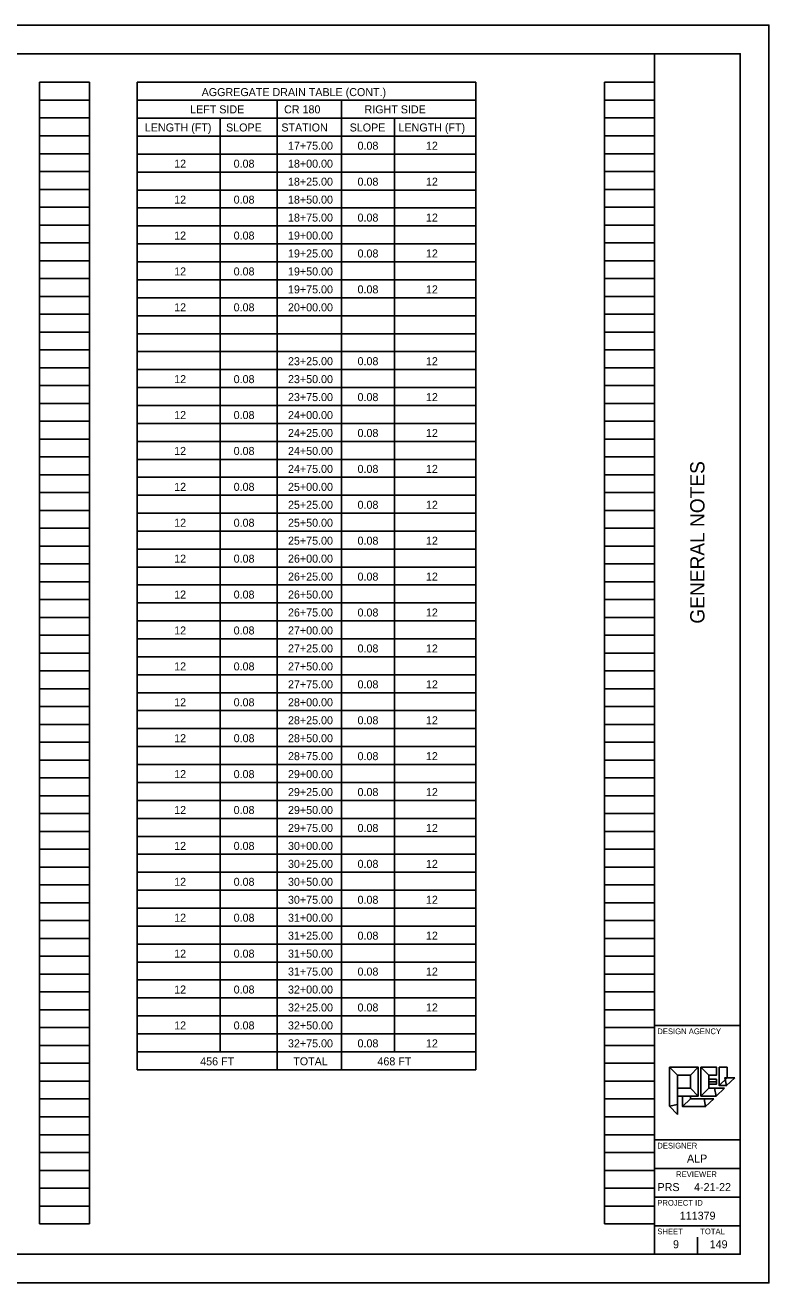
# Model space of a CAD drawing. Extents: x -0.5 to 34, y 0 to 22.
# Drawn here: x 21 to 34, y 0 to 22 of the extents above; entities that cross this region are included whole.
import ezdxf

# ---------------------------------------------------------------- set-up
doc = ezdxf.new("R2010")
doc.units = 0
for name, color, linetype in [('Default', 7, 'Continuous'), ('SC_Scratch1', 7, 'Continuous'), ('SH_Border', 7, 'Continuous'), ('SH_Cut_Line', 7, 'Continuous'), ('SH_Data', 7, 'Continuous'), ('SH_Text', 7, 'Continuous')]:
    doc.layers.add(name, color=color, linetype=linetype)

msp = doc.modelspace()

# ---------------------------------------------------------------- linework, layer by layer
at = {"layer": 'Default'}
msp.add_line((32.95, 3.519), (33.087, 3.519), dxfattribs=at)
for points in [[(32.264, 3.093), (32.264, 3.77), (32.401, 3.633), (32.401, 3.121)], [(32.264, 3.77), (32.767, 3.77), (32.63, 3.633), (32.401, 3.633)], [(32.767, 3.77), (32.767, 3.267), (32.63, 3.404), (32.63, 3.633)], [(32.812, 3.267), (32.812, 3.77), (32.95, 3.633), (32.95, 3.404)], [(32.812, 3.77), (33.087, 3.77), (33.087, 3.633), (32.95, 3.633)], [(33.132, 3.45), (33.132, 3.77), (33.27, 3.77), (33.27, 3.587)], [(33.087, 3.56), (33.087, 3.477), (32.951, 3.477), (32.951, 3.56)], [(33.261, 3.45), (33.132, 3.45), (33.27, 3.587), (33.233, 3.587)], [(33.407, 3.587), (33.261, 3.45), (33.233, 3.587)], [(32.767, 3.267), (32.401, 3.267), (32.401, 3.404), (32.63, 3.404)], [(33.078, 3.267), (32.812, 3.267), (32.95, 3.404), (33.05, 3.404)], [(33.224, 3.404), (33.078, 3.267), (33.05, 3.404)], [(32.401, 2.947), (32.264, 3.093), (32.401, 3.121)], [(32.492, 3.084), (32.492, 3.267), (32.63, 3.267), (32.63, 3.221)], [(32.895, 3.084), (32.492, 3.084), (32.63, 3.221), (32.867, 3.221)], [(33.041, 3.221), (32.895, 3.084), (32.867, 3.221)]]:
    msp.add_lwpolyline(points, close=True, dxfattribs=at)
at = {"layer": 'SC_Scratch1'}
for p, q in [((21.25, 1.032), (21.25, 21)), ((21.25, 21), (22.125, 21)), ((22.125, 1.032), (22.125, 21)), ((31.125, 1.032), (31.125, 21)), ((31.125, 21), (32, 21)), ((32, 1.032), (32, 21)), ((21.25, 20.688), (22.125, 20.688)), ((31.125, 20.688), (32, 20.688)), ((21.25, 20.376), (22.125, 20.376)), ((31.125, 20.376), (32, 20.376)), ((21.25, 20.064), (22.125, 20.064)), ((31.125, 20.064), (32, 20.064)), ((21.25, 19.752), (22.125, 19.752)), ((31.125, 19.752), (32, 19.752)), ((21.25, 19.44), (22.125, 19.44)), ((31.125, 19.44), (32, 19.44)), ((21.25, 19.128), (22.125, 19.128)), ((31.125, 19.128), (32, 19.128)), ((21.25, 18.816), (22.125, 18.816)), ((31.125, 18.816), (32, 18.816)), ((21.25, 18.504), (22.125, 18.504)), ((31.125, 18.504), (32, 18.504)), ((21.25, 18.192), (22.125, 18.192)), ((31.125, 18.192), (32, 18.192)), ((21.25, 17.88), (22.125, 17.88)), ((31.125, 17.88), (32, 17.88)), ((21.25, 17.568), (22.125, 17.568)), ((31.125, 17.568), (32, 17.568)), ((21.25, 17.256), (22.125, 17.256)), ((31.125, 17.256), (32, 17.256)), ((21.25, 16.944), (22.125, 16.944)), ((31.125, 16.944), (32, 16.944)), ((21.25, 16.632), (22.125, 16.632)), ((31.125, 16.632), (32, 16.632)), ((21.25, 16.32), (22.125, 16.32)), ((31.125, 16.32), (32, 16.32)), ((21.25, 16.008), (22.125, 16.008)), ((31.125, 16.008), (32, 16.008)), ((21.25, 15.696), (22.125, 15.696)), ((31.125, 15.696), (32, 15.696)), ((21.25, 15.384), (22.125, 15.384)), ((31.125, 15.384), (32, 15.384)), ((21.25, 15.072), (22.125, 15.072)), ((31.125, 15.072), (32, 15.072)), ((21.25, 14.76), (22.125, 14.76)), ((31.125, 14.76), (32, 14.76)), ((21.25, 14.448), (22.125, 14.448)), ((31.125, 14.448), (32, 14.448)), ((21.25, 14.136), (22.125, 14.136)), ((31.125, 14.136), (32, 14.136)), ((21.25, 13.824), (22.125, 13.824)), ((31.125, 13.824), (32, 13.824)), ((21.25, 13.512), (22.125, 13.512)), ((31.125, 13.512), (32, 13.512)), ((21.25, 13.2), (22.125, 13.2)), ((31.125, 13.2), (32, 13.2)), ((21.25, 12.888), (22.125, 12.888)), ((31.125, 12.888), (32, 12.888)), ((21.25, 12.576), (22.125, 12.576)), ((31.125, 12.576), (32, 12.576)), ((21.25, 12.264), (22.125, 12.264)), ((31.125, 12.264), (32, 12.264)), ((21.25, 11.952), (22.125, 11.952)), ((31.125, 11.952), (32, 11.952)), ((21.25, 11.64), (22.125, 11.64)), ((31.125, 11.64), (32, 11.64)), ((21.25, 11.328), (22.125, 11.328)), ((31.125, 11.328), (32, 11.328)), ((21.25, 11.016), (22.125, 11.016)), ((31.125, 11.016), (32, 11.016)), ((21.25, 10.704), (22.125, 10.704)), ((31.125, 10.704), (32, 10.704)), ((21.25, 10.392), (22.125, 10.392)), ((31.125, 10.392), (32, 10.392)), ((21.25, 10.08), (22.125, 10.08)), ((31.125, 10.08), (32, 10.08)), ((21.25, 9.768), (22.125, 9.768)), ((31.125, 9.768), (32, 9.768)), ((21.25, 9.456), (22.125, 9.456)), ((31.125, 9.456), (32, 9.456)), ((21.25, 9.144), (22.125, 9.144)), ((31.125, 9.144), (32, 9.144)), ((21.25, 8.832), (22.125, 8.832)), ((31.125, 8.832), (32, 8.832)), ((21.25, 8.52), (22.125, 8.52)), ((31.125, 8.52), (32, 8.52)), ((21.25, 8.208), (22.125, 8.208)), ((31.125, 8.208), (32, 8.208)), ((21.25, 7.896), (22.125, 7.896)), ((31.125, 7.896), (32, 7.896)), ((21.25, 7.584), (22.125, 7.584)), ((31.125, 7.584), (32, 7.584)), ((21.25, 7.272), (22.125, 7.272)), ((31.125, 7.272), (32, 7.272)), ((21.25, 6.96), (22.125, 6.96)), ((31.125, 6.96), (32, 6.96)), ((21.25, 6.648), (22.125, 6.648)), ((31.125, 6.648), (32, 6.648)), ((21.25, 6.336), (22.125, 6.336)), ((31.125, 6.336), (32, 6.336)), ((21.25, 6.024), (22.125, 6.024)), ((31.125, 6.024), (32, 6.024)), ((21.25, 5.712), (22.125, 5.712)), ((31.125, 5.712), (32, 5.712)), ((21.25, 5.4), (22.125, 5.4)), ((31.125, 5.4), (32, 5.4)), ((21.25, 5.088), (22.125, 5.088)), ((31.125, 5.088), (32, 5.088)), ((21.25, 4.776), (22.125, 4.776)), ((31.125, 4.776), (32, 4.776)), ((21.25, 4.464), (22.125, 4.464)), ((31.125, 4.464), (32, 4.464)), ((21.25, 4.152), (22.125, 4.152)), ((31.125, 4.152), (32, 4.152)), ((21.25, 3.84), (22.125, 3.84)), ((31.125, 3.84), (32, 3.84)), ((21.25, 3.528), (22.125, 3.528)), ((31.125, 3.528), (32, 3.528)), ((21.25, 3.216), (22.125, 3.216)), ((31.125, 3.216), (32, 3.216)), ((21.25, 2.904), (22.125, 2.904)), ((31.125, 2.904), (32, 2.904)), ((21.25, 2.592), (22.125, 2.592)), ((31.125, 2.592), (32, 2.592)), ((21.25, 2.28), (22.125, 2.28)), ((31.125, 2.28), (32, 2.28)), ((21.25, 1.968), (22.125, 1.968)), ((31.125, 1.968), (32, 1.968)), ((21.25, 1.656), (22.125, 1.656)), ((31.125, 1.656), (32, 1.656)), ((21.25, 1.344), (22.125, 1.344)), ((31.125, 1.344), (32, 1.344)), ((21.25, 1.032), (22.125, 1.032)), ((31.125, 1.032), (32, 1.032))]:
    msp.add_line(p, q, dxfattribs=at)
at = {"layer": 'SH_Border'}
for p, q in [((32, 0.5), (32, 21.5)), ((32, 4.5), (33.5, 4.5)), ((32, 2.5), (33.5, 2.5)), ((32, 2), (33.5, 2)), ((32, 1.5), (33.5, 1.5)), ((32, 1), (33.5, 1))]:
    msp.add_line(p, q, dxfattribs=at)
msp.add_lwpolyline([(1.5, 21.5), (33.5, 21.5), (33.5, 0.5), (1.5, 0.5)], close=True, dxfattribs=at)
at = {"layer": 'SH_Cut_Line'}
msp.add_lwpolyline([(0, 0), (34, 0), (34, 22), (0, 22)], close=True, dxfattribs=at)
at = {"layer": 'SH_Data'}
for p, q in [((32.75, 3.5), (32.75, 3.5)), ((32.75, 0.5), (32.75, 0.8))]:
    msp.add_line(p, q, dxfattribs=at)
at = {"layer": 'SH_Text'}
for p, q in [((22.956, 21), (28.88, 21)), ((22.956, 21), (22.956, 3.728)), ((28.88, 21), (28.88, 3.728)), ((22.956, 20.686), (28.88, 20.686)), ((25.404, 20.686), (25.404, 3.728)), ((26.531, 20.686), (26.531, 3.728)), ((22.956, 20.372), (28.88, 20.372)), ((24.406, 20.372), (24.406, 4.042)), ((27.457, 20.372), (27.457, 4.042)), ((22.956, 20.058), (28.88, 20.058)), ((22.956, 19.744), (28.88, 19.744)), ((22.956, 19.43), (28.88, 19.43)), ((22.956, 19.116), (28.88, 19.116)), ((22.956, 18.802), (28.88, 18.802)), ((22.956, 18.488), (28.88, 18.488)), ((22.956, 18.174), (28.88, 18.174)), ((22.956, 17.86), (28.88, 17.86)), ((22.956, 17.546), (28.88, 17.546)), ((22.956, 17.231), (28.88, 17.231)), ((22.956, 16.917), (28.88, 16.917)), ((22.956, 16.603), (28.88, 16.603)), ((22.956, 16.289), (28.88, 16.289)), ((22.956, 15.975), (28.88, 15.975)), ((22.956, 15.661), (28.88, 15.661)), ((22.956, 15.347), (28.88, 15.347)), ((22.956, 15.033), (28.88, 15.033)), ((22.956, 14.719), (28.88, 14.719)), ((22.956, 14.405), (28.88, 14.405)), ((22.956, 14.091), (28.88, 14.091)), ((22.956, 13.777), (28.88, 13.777)), ((22.956, 13.463), (28.88, 13.463)), ((22.956, 13.149), (28.88, 13.149)), ((22.956, 12.835), (28.88, 12.835)), ((22.956, 12.521), (28.88, 12.521)), ((22.956, 12.207), (28.88, 12.207)), ((22.956, 11.893), (28.88, 11.893)), ((22.956, 11.579), (28.88, 11.579)), ((22.956, 11.265), (28.88, 11.265)), ((22.956, 10.951), (28.88, 10.951)), ((22.956, 10.637), (28.88, 10.637)), ((22.956, 10.323), (28.88, 10.323)), ((22.956, 10.009), (28.88, 10.009)), ((22.956, 9.695), (28.88, 9.695)), ((22.956, 9.38), (28.88, 9.38)), ((22.956, 9.066), (28.88, 9.066)), ((22.956, 8.752), (28.88, 8.752)), ((22.956, 8.438), (28.88, 8.438)), ((22.956, 8.124), (28.88, 8.124)), ((22.956, 7.81), (28.88, 7.81)), ((22.956, 7.496), (28.88, 7.496)), ((22.956, 7.182), (28.88, 7.182)), ((22.956, 6.868), (28.88, 6.868)), ((22.956, 6.554), (28.88, 6.554)), ((22.956, 6.24), (28.88, 6.24)), ((22.956, 5.926), (28.88, 5.926)), ((22.956, 5.612), (28.88, 5.612)), ((22.956, 5.298), (28.88, 5.298)), ((22.956, 4.984), (28.88, 4.984)), ((22.956, 4.67), (28.88, 4.67)), ((22.956, 4.356), (28.88, 4.356)), ((22.956, 4.042), (28.88, 4.042)), ((22.956, 3.728), (28.88, 3.728))]:
    msp.add_line(p, q, dxfattribs=at)

# ---------------------------------------------------------------- texts
at = {"layer": 'SH_Data'}
msp.add_text('GENERAL NOTES', height=0.25, rotation=90, dxfattribs=at).set_placement((32.875, 11.531))
for s, height, p in [('DESIGN AGENCY', 0.1, (32.05, 4.35)), ('DESIGNER', 0.1, (32.05, 2.35)), ('ALP', 0.14, (32.569, 2.105)), ('REVIEWER', 0.1, (32.378, 1.85)), ('PRS', 0.14, (32.054, 1.605)), ('4-21-22', 0.14, (32.693, 1.605)), ('PROJECT ID', 0.1, (32.05, 1.35)), ('111379', 0.14, (32.443, 1.105)), ('SHEET', 0.1, (32.05, 0.85)), ('TOTAL', 0.1, (32.8, 0.85)), ('9', 0.14, (32.325, 0.605)), ('149', 0.14, (32.966, 0.605))]:
    msp.add_text(s, height=height, dxfattribs=at).set_placement(p)
at = {"layer": 'SH_Text'}
for s, p in [('AGGREGATE DRAIN TABLE (CONT.)', (24.084, 20.759)), ('LEFT SIDE', (23.882, 20.457)), ('CR 180', (25.525, 20.457)), ('RIGHT SIDE', (26.931, 20.457)), ('LENGTH (FT)', (23.09, 20.14)), ('SLOPE', (24.51, 20.14)), ('STATION', (25.477, 20.14)), ('SLOPE', (26.671, 20.14)), ('LENGTH (FT)', (27.525, 20.14)), ('17+75.00', (25.593, 19.821)), ('0.08', (26.809, 19.821)), ('12', (28.005, 19.821)), ('12', (23.603, 19.507)), ('0.08', (24.643, 19.507)), ('18+00.00', (25.593, 19.507)), ('18+25.00', (25.593, 19.192)), ('0.08', (26.809, 19.192)), ('12', (28.005, 19.192)), ('12', (23.603, 18.878)), ('0.08', (24.643, 18.878)), ('18+50.00', (25.593, 18.878)), ('18+75.00', (25.593, 18.564)), ('0.08', (26.809, 18.564)), ('12', (28.005, 18.564)), ('12', (23.603, 18.25)), ('0.08', (24.643, 18.25)), ('19+00.00', (25.593, 18.25)), ('19+25.00', (25.593, 17.936)), ('0.08', (26.809, 17.936)), ('12', (28.005, 17.936)), ('12', (23.603, 17.622)), ('0.08', (24.643, 17.622)), ('19+50.00', (25.593, 17.622)), ('19+75.00', (25.593, 17.308)), ('0.08', (26.809, 17.308)), ('12', (28.005, 17.308)), ('12', (23.603, 16.994)), ('0.08', (24.643, 16.994)), ('20+00.00', (25.593, 16.994)), ('23+25.00', (25.593, 16.052)), ('0.08', (26.809, 16.052)), ('12', (28.005, 16.052)), ('12', (23.603, 15.738)), ('0.08', (24.643, 15.738)), ('23+50.00', (25.593, 15.738)), ('23+75.00', (25.593, 15.424)), ('0.08', (26.809, 15.424)), ('12', (28.005, 15.424)), ('12', (23.603, 15.11)), ('0.08', (24.643, 15.11)), ('24+00.00', (25.593, 15.11)), ('24+25.00', (25.593, 14.796)), ('0.08', (26.809, 14.796)), ('12', (28.005, 14.796)), ('12', (23.603, 14.482)), ('0.08', (24.643, 14.482)), ('24+50.00', (25.593, 14.482)), ('24+75.00', (25.593, 14.168)), ('0.08', (26.809, 14.168)), ('12', (28.005, 14.168)), ('12', (23.603, 13.854)), ('0.08', (24.643, 13.854)), ('25+00.00', (25.593, 13.854)), ('25+25.00', (25.593, 13.54)), ('0.08', (26.809, 13.54)), ('12', (28.005, 13.54)), ('12', (23.603, 13.226)), ('0.08', (24.643, 13.226)), ('25+50.00', (25.593, 13.226)), ('25+75.00', (25.593, 12.912)), ('0.08', (26.809, 12.912)), ('12', (28.005, 12.912)), ('12', (23.603, 12.598)), ('0.08', (24.643, 12.598)), ('26+00.00', (25.593, 12.598)), ('26+25.00', (25.593, 12.284)), ('0.08', (26.809, 12.284)), ('12', (28.005, 12.284)), ('12', (23.603, 11.97)), ('0.08', (24.643, 11.97)), ('26+50.00', (25.593, 11.97)), ('26+75.00', (25.593, 11.656)), ('0.08', (26.809, 11.656)), ('12', (28.005, 11.656)), ('12', (23.603, 11.342)), ('0.08', (24.643, 11.342)), ('27+00.00', (25.593, 11.342)), ('27+25.00', (25.593, 11.027)), ('0.08', (26.809, 11.027)), ('12', (28.005, 11.027)), ('12', (23.603, 10.713)), ('0.08', (24.643, 10.713)), ('27+50.00', (25.593, 10.713)), ('27+75.00', (25.593, 10.399)), ('0.08', (26.809, 10.399)), ('12', (28.005, 10.399)), ('12', (23.603, 10.085)), ('0.08', (24.643, 10.085)), ('28+00.00', (25.593, 10.085)), ('28+25.00', (25.593, 9.771)), ('0.08', (26.809, 9.771)), ('12', (28.005, 9.771)), ('12', (23.603, 9.457)), ('0.08', (24.643, 9.457)), ('28+50.00', (25.593, 9.457)), ('28+75.00', (25.593, 9.143)), ('0.08', (26.809, 9.143)), ('12', (28.005, 9.143)), ('12', (23.603, 8.829)), ('0.08', (24.643, 8.829)), ('29+00.00', (25.593, 8.829)), ('29+25.00', (25.593, 8.515)), ('0.08', (26.809, 8.515)), ('12', (28.005, 8.515)), ('12', (23.603, 8.201)), ('0.08', (24.643, 8.201)), ('29+50.00', (25.593, 8.201)), ('29+75.00', (25.593, 7.887)), ('0.08', (26.809, 7.887)), ('12', (28.005, 7.887)), ('12', (23.603, 7.573)), ('0.08', (24.643, 7.573)), ('30+00.00', (25.593, 7.573)), ('30+25.00', (25.593, 7.259)), ('0.08', (26.809, 7.259)), ('12', (28.005, 7.259)), ('12', (23.603, 6.945)), ('0.08', (24.643, 6.945)), ('30+50.00', (25.593, 6.945)), ('30+75.00', (25.593, 6.631)), ('0.08', (26.809, 6.631)), ('12', (28.005, 6.631)), ('12', (23.603, 6.317)), ('0.08', (24.643, 6.317)), ('31+00.00', (25.593, 6.317)), ('31+25.00', (25.593, 6.003)), ('0.08', (26.809, 6.003)), ('12', (28.005, 6.003)), ('12', (23.603, 5.689)), ('0.08', (24.643, 5.689)), ('31+50.00', (25.593, 5.689)), ('31+75.00', (25.593, 5.375)), ('0.08', (26.809, 5.375)), ('12', (28.005, 5.375)), ('12', (23.603, 5.061)), ('0.08', (24.643, 5.061)), ('32+00.00', (25.593, 5.061)), ('32+25.00', (25.593, 4.747)), ('0.08', (26.809, 4.747)), ('12', (28.005, 4.747)), ('12', (23.603, 4.433)), ('0.08', (24.643, 4.433)), ('32+50.00', (25.593, 4.433)), ('32+75.00', (25.593, 4.119)), ('0.08', (26.809, 4.119)), ('12', (28.005, 4.119)), ('456 FT', (24.058, 3.805)), ('TOTAL', (25.685, 3.805)), ('468 FT', (27.157, 3.805))]:
    msp.add_text(s, height=0.14, dxfattribs=at).set_placement(p)

doc.saveas('drawing.dxf')
